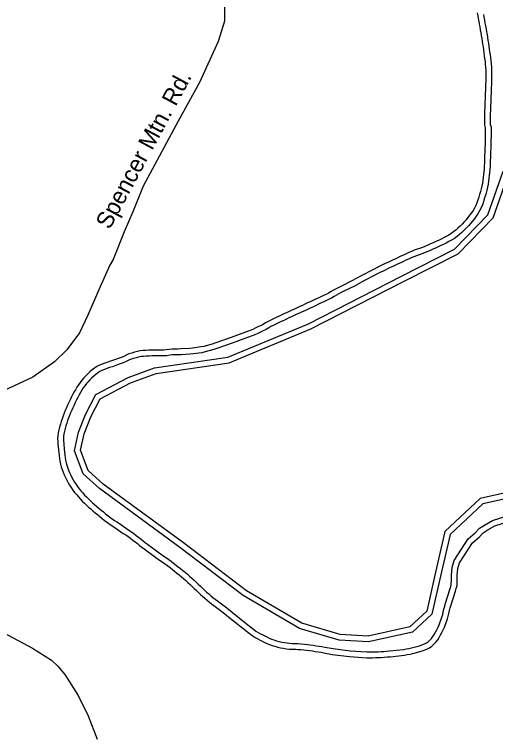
# Model space of a CAD drawing. Extents: x 1364363 to 1407445, y 538563 to 573342.
# Drawn here: x 1371427 to 1374145, y 564968 to 569065 of the extents above; entities that cross this region are included whole.
import ezdxf

# ---------------------------------------------------------------- set-up
doc = ezdxf.new("R2010")
doc.units = 0
for name, color, linetype in [('Exist Hydrographic Buffer Line', 7, 'Continuous'), ('Exist Hydrographic Creek Double Shore', 7, 'Continuous'), ('Exist Road Secondary Type 51 Attributed', 7, 'Continuous'), ('Exist Road Secondary Type 51 Label', 7, 'Continuous')]:
    doc.layers.add(name, color=color, linetype=linetype)

msp = doc.modelspace()

# ---------------------------------------------------------------- linework, layer by layer
at = {"layer": 'Exist Hydrographic Buffer Line'}
for points in [[(1374076.3, 569064.9), (1374079.3, 569048.8), (1374082.4, 569032.7), (1374085.4, 569016.4), (1374088.3, 569000.3), (1374091.3, 568983.9), (1374094.2, 568967.3), (1374096.8, 568950.9), (1374099.3, 568934.7), (1374101.9, 568918.5), (1374104.5, 568902.2), (1374107, 568885.8), (1374109.3, 568869.4), (1374111.7, 568853.1), (1374114, 568836.5), (1374116.1, 568819.9), (1374118.1, 568803.5), (1374120, 568786.6), (1374121.5, 568769.4), (1374122.5, 568751.9), (1374122.8, 568734.5), (1374122.8, 568717.5), (1374122.5, 568700.7), (1374122.2, 568684.2), (1374121.8, 568667.5), (1374121.1, 568650.9), (1374120.5, 568634.5), (1374119.9, 568618), (1374119.2, 568601.6), (1374118.6, 568585.2), (1374117.9, 568568.7), (1374117.1, 568552.4), (1374116.5, 568536.1), (1374115.9, 568520), (1374115.5, 568503.8), (1374115.1, 568487.4), (1374114.8, 568471.5), (1374114.9, 568455.9), (1374115.4, 568443.7), (1374119.5, 568427.8), (1374119.7, 568407.1), (1374119.5, 568390.1), (1374118.3, 568338.3), (1374116, 568256.1), (1374115.5, 568239.6), (1374115, 568223.1), (1374114.3, 568206.3), (1374113.4, 568188.7), (1374103.3, 568105.6), (1374100.2, 568087.6), (1374096, 568069.8), (1374091.3, 568053.4)], [(1374268.4, 566339.1), (1374074.1, 566297.1), (1373889, 566122.4), (1373833.5, 565886.1), (1373785.8, 565671.5), (1373676.3, 565569.8), (1373427.3, 565515), (1373261, 565525.3), (1373037.6, 565590.9), (1372719.5, 565777.5), (1372361.6, 566048.5), (1371906.2, 566382.4), (1371815.1, 566466.2), (1371765.6, 566596.4), (1371788.9, 566701.2), (1371827.8, 566801.1), (1371887, 566914.9), (1372068.6, 567011.8), (1372218.3, 567064.9), (1372631.3, 567126.2), (1373087.9, 567315.2), (1373613.4, 567584.4), (1373913.2, 567736.6), (1374102.2, 567932.2), (1374188.8, 568178.4)], [(1374091.2, 568053), (1374086.4, 568037), (1374081.4, 568021), (1374076.1, 568004.8), (1374070.4, 567988.6), (1374063.9, 567971.5), (1374055.2, 567953.8), (1374045, 567937.6), (1374035.1, 567923.5), (1374025.2, 567909.6), (1374014.6, 567895.7), (1374003.4, 567881.9), (1373991.5, 567868.7), (1373979.6, 567856.3), (1373967.5, 567844.1), (1373955, 567832), (1373941.7, 567819.9), (1373927.3, 567808.3), (1373912.2, 567797.6), (1373896.8, 567788.2), (1373881.7, 567779.8), (1373866.5, 567771.8), (1373851.2, 567764.3), (1373836, 567757), (1373820.6, 567750), (1373805.2, 567743.2), (1373789.9, 567736.5), (1373774.8, 567730), (1373743.5, 567716.7), (1373697.6, 567700), (1373683.5, 567693.9), (1373668.7, 567687.3), (1373653.9, 567680.7), (1373639, 567673.9), (1373624.2, 567667.2), (1373609.4, 567660.4), (1373594.6, 567653.4), (1373579.6, 567646.5), (1373564.9, 567639.7), (1373550.2, 567632.7), (1373535.4, 567625.7), (1373520.8, 567618.7), (1373506.2, 567611.6), (1373491.6, 567604.4), (1373477.2, 567597.2), (1373463, 567589.9), (1373405.3, 567559.1), (1373347.1, 567528.6), (1373288.4, 567498.5), (1373273.5, 567491.2), (1373259, 567483.9), (1373245.7, 567477.1), (1373233.1, 567469.3), (1373217.8, 567459.6), (1373201.1, 567451.7), (1373186.3, 567444.7), (1373171.4, 567437.6), (1373156.4, 567430.6), (1373141.6, 567423.7), (1373126.7, 567416.7), (1373111.8, 567409.7), (1373096.9, 567402.9), (1373082, 567395.9), (1373067, 567389.1), (1373052.2, 567382.2), (1373037.2, 567375.3), (1373022.3, 567368.4), (1373007.5, 567361.5), (1372992.6, 567354.6), (1372977.7, 567347.7), (1372962.9, 567340.8), (1372948, 567333.9), (1372933.1, 567326.9), (1372918.4, 567320), (1372903.7, 567313), (1372888.8, 567306), (1372875.5, 567299.7), (1372863.1, 567292.2), (1372848, 567282.8), (1372831.8, 567274.7), (1372816.6, 567267.4), (1372801.3, 567260.2), (1372785.2, 567253), (1372708.1, 567223.7), (1372661.9, 567206.5), (1372569.2, 567174.3), (1372552.6, 567168.7), (1372504.1, 567155.5), (1372486, 567151.3), (1372435.4, 567144), (1372417.6, 567142.8), (1372368.5, 567140.1), (1372351.5, 567139.2), (1372334.5, 567138.9), (1372317.6, 567138.6)], [(1372321.8, 567139), (1372305.2, 567136.6), (1372287.3, 567134.4), (1372269.3, 567133.6), (1372252.4, 567133.3), (1372235.6, 567133.1), (1372219.2, 567133), (1372203, 567132.8), (1372187.1, 567132.5), (1372171.6, 567131.8), (1372156.5, 567130.7), (1372142.1, 567129), (1372128.2, 567126.3), (1372113.9, 567122.6), (1372098.9, 567118.1), (1372085.1, 567113.8), (1372072.5, 567108.3), (1372057.3, 567100.6), (1372040.3, 567094), (1372024.5, 567088), (1372009, 567082.4), (1371980, 567072)], [(1371979.1, 567071.7), (1371963.7, 567066.7), (1371949.1, 567061.8), (1371934.7, 567056), (1371920.4, 567050.3), (1371908.6, 567044.5), (1371897.8, 567037.5), (1371886.3, 567028.6), (1371874.6, 567018.9), (1371863.4, 567008.7), (1371852.5, 566998), (1371842.2, 566987.2), (1371832.8, 566976.2), (1371824, 566964.5), (1371815.3, 566951.9), (1371806.9, 566938.8), (1371798.9, 566925.6), (1371791.4, 566912.3), (1371784.3, 566898.5), (1371777.3, 566884.2), (1371770.4, 566869.6), (1371763.5, 566854.9), (1371756.6, 566840.2), (1371749.9, 566825.5), (1371743.5, 566811), (1371737.6, 566796.6), (1371732.1, 566782.2), (1371727, 566767.5), (1371722, 566752.3), (1371717.3, 566737.2), (1371713, 566722.2), (1371709.3, 566707.2), (1371705.9, 566692.3), (1371703.5, 566678.9), (1371702.8, 566666.2), (1371703.4, 566651.8), (1371704.6, 566636.2), (1371707.7, 566604.7), (1371710.9, 566573.4), (1371713, 566558.3), (1371715.6, 566543.1), (1371718.5, 566528.9), (1371722.5, 566515.1), (1371732, 566486.6), (1371737.9, 566473.4), (1371744.5, 566459.1), (1371751.4, 566445.2), (1371758.6, 566431.8), (1371766.3, 566418.7), (1371774.5, 566405.8), (1371783.1, 566393.5), (1371792.3, 566381.3), (1371802, 566369.2), (1371812, 566357.5), (1371822.4, 566346.1), (1371833.1, 566334.9), (1371844.3, 566323.9), (1371855.8, 566313), (1371867.5, 566302.2), (1371879.3, 566291.7), (1371891.5, 566281.3), (1371903.7, 566270.9), (1371916.3, 566260.6), (1371928.9, 566250.2), (1371941.3, 566240.1), (1371953.5, 566230.4), (1371966.1, 566221.2), (1371979.2, 566211.9), (1371992.4, 566202.6), (1372005.8, 566193.4), (1372019.3, 566184.1), (1372032.8, 566174.8), (1372046.3, 566165.6), (1372059.9, 566156.3), (1372073.6, 566146.8), (1372087.1, 566137.4), (1372100.7, 566127.8), (1372114.6, 566117.8), (1372128.3, 566107.4), (1372141.6, 566096.7), (1372154.2, 566086.2), (1372166.4, 566076.4), (1372178.9, 566067.1), (1372244.7, 566019.2), (1372257.7, 566010), (1372271.1, 566000.8), (1372284.8, 565991.5), (1372298.8, 565981.6), (1372312.4, 565971.4), (1372325.8, 565961.2), (1372351.9, 565940.6), (1372364.9, 565930.1), (1372377.8, 565919.6), (1372390.6, 565908.9), (1372403.4, 565898.1), (1372416.1, 565887.1), (1372428.8, 565875.8), (1372441.1, 565864.3), (1372453.2, 565853)], [(1373017.6, 565506), (1373029.9, 565505.6), (1373047.3, 565504.6), (1373064.8, 565503), (1373081.7, 565500.9), (1373098.3, 565498.7), (1373114.9, 565496.3), (1373131.4, 565493.7), (1373147.7, 565491.1), (1373164.1, 565488.4), (1373180.6, 565485.6), (1373227.7, 565476.9), (1373322.7, 565464.6), (1373418.5, 565458), (1373433.5, 565458.1), (1373449.6, 565458.4), (1373465.6, 565458.9), (1373481.7, 565459.5), (1373497.8, 565460.3), (1373513.9, 565461.3), (1373529.7, 565462.4), (1373545.3, 565463.9), (1373625.6, 565472.9), (1373640.6, 565475.3), (1373655.9, 565478.1), (1373670.6, 565481.3), (1373715.4, 565493.6), (1373728.8, 565498.5), (1373743.1, 565504.4), (1373754.8, 565509.6), (1373763.8, 565516), (1373773.7, 565525), (1373783.4, 565535.1), (1373791.4, 565545.1), (1373798.5, 565556.6), (1373805.9, 565570), (1373813.1, 565583.9), (1373820, 565597.9), (1373826, 565611.1), (1373842, 565655.4), (1373846.4, 565669.2), (1373849.9, 565683.9), (1373853.6, 565699.8), (1373857.6, 565716.6), (1373862.4, 565733.4), (1373886.6, 565812), (1373891.6, 565827.7), (1373895, 565838.7), (1373895.2, 565866.7), (1373895.2, 565893.5), (1373900.3, 565936.8), (1373911.4, 565975.8), (1373989.5, 566097.9), (1374030.4, 566131.6), (1374054.8, 566158.4), (1374081.9, 566174.7), (1374128.2, 566201.5), (1374216.8, 566231.1)], [(1372453.3, 565852.8), (1372465.3, 565841.5), (1372477.1, 565830.1), (1372488.8, 565818.9), (1372500.6, 565807.9), (1372512.4, 565797.1), (1372524.2, 565786.6), (1372536.2, 565776.2), (1372548.3, 565766.2), (1372560.7, 565756.4), (1372573.3, 565746.9), (1372626.6, 565707.9), (1372678.3, 565666.1), (1372754.6, 565604), (1372767.1, 565593.7), (1372779.1, 565584.3), (1372791, 565575.7), (1372803, 565568.2), (1372816, 565561.3), (1372830.3, 565554.3), (1372852.3, 565543.4)], [(1372853.1, 565542.9), (1372866.6, 565535.8), (1372878.8, 565530.4), (1372892.5, 565526.2), (1372907.7, 565521.7), (1372922.8, 565517.6), (1372937.7, 565514), (1372952.3, 565511.1), (1372966.8, 565508.9), (1372981.5, 565507.6), (1372997, 565506.8), (1373013.2, 565506.2), (1373017.6, 565506)]]:
    msp.add_lwpolyline(points, dxfattribs=at)
at = {"layer": 'Exist Hydrographic Creek Double Shore'}
for points in [[(1374041.1, 569075), (1374044.1, 569059)], [(1374044.1, 569059), (1374047, 569042.8), (1374050.1, 569026.7), (1374053.1, 569010.5), (1374056.1, 568994.4), (1374059, 568978.2), (1374061.8, 568962), (1374064.4, 568945.8), (1374066.9, 568929.6), (1374069.5, 568913.4), (1374072.1, 568897.2), (1374074.5, 568881), (1374076.9, 568864.7), (1374079.2, 568848.5), (1374081.5, 568832.2), (1374083.5, 568815.9), (1374085.5, 568799.7), (1374087.3, 568783.4), (1374088.8, 568767), (1374089.7, 568750.7), (1374090, 568734.2), (1374090, 568717.8), (1374089.7, 568701.3), (1374089.4, 568684.9), (1374089, 568668.5), (1374088.4, 568652.2), (1374087.7, 568635.8), (1374087.1, 568619.4), (1374086.4, 568603), (1374085.8, 568586.6), (1374085.1, 568570.2), (1374084.4, 568553.8), (1374083.7, 568537.4), (1374083.1, 568521), (1374082.7, 568504.6), (1374082.3, 568488.1), (1374082, 568471.7), (1374082.1, 568455.2), (1374082.7, 568438.9), (1374086.7, 568423.4), (1374086.9, 568407.1), (1374086.7, 568390.7), (1374085.5, 568339.1), (1374083.2, 568257), (1374082.7, 568240.6), (1374082.2, 568224.3), (1374081.5, 568207.9), (1374080.7, 568191.5), (1374070.8, 568110.3), (1374068.1, 568094.1), (1374064.3, 568078.1), (1374059.8, 568062.4)], [(1374268.6, 566372.7), (1374058.3, 566327.2), (1373859.3, 566139.5), (1373801.5, 565893.4), (1373756, 565688.6), (1373660.5, 565599.9), (1373424.7, 565548.1), (1373266.7, 565557.8), (1373050.7, 565621.3), (1372737.8, 565804.8), (1372381.2, 566074.8), (1371927.1, 566407.8), (1371843, 566485.2), (1371799.8, 566598.9), (1371820.4, 566691.6), (1371857.7, 566787.5), (1371911.4, 566890.7), (1372081.9, 566981.7), (1372226.3, 567032.9), (1372640.1, 567094.3), (1373101.7, 567285.4), (1373628.3, 567555.1), (1373933, 567709.8), (1374130.8, 567914.6), (1374221.6, 568172.6)], [(1374059.8, 568062.4), (1374055, 568046.7), (1374050.1, 568031), (1374045, 568015.3), (1374039.6, 567999.9), (1374033.7, 567984.6), (1374026.5, 567969.8), (1374017.7, 567955.9), (1374008.3, 567942.4), (1373998.7, 567929.1), (1373988.8, 567915.9), (1373978.4, 567903.2), (1373967.5, 567891.1), (1373956.1, 567879.2), (1373944.4, 567867.4), (1373932.5, 567855.9), (1373920.3, 567844.8), (1373907.5, 567834.5), (1373894.2, 567825), (1373880.3, 567816.6), (1373866.1, 567808.6), (1373851.6, 567801.1), (1373836.9, 567793.8), (1373822.1, 567786.7), (1373807.1, 567779.9), (1373792.1, 567773.2), (1373776.9, 567766.7), (1373761.8, 567760.2), (1373731.5, 567747.2), (1373685.4, 567730.5), (1373670.4, 567723.9), (1373655.4, 567717.3), (1373640.4, 567710.6), (1373625.5, 567703.8), (1373610.5, 567697), (1373595.6, 567690.1), (1373580.8, 567683.2), (1373565.8, 567676.3), (1373550.9, 567669.4), (1373536.2, 567662.3), (1373521.3, 567655.3), (1373506.5, 567648.2), (1373491.8, 567641.1), (1373477, 567633.8), (1373462.3, 567626.5), (1373447.8, 567619), (1373389.9, 567588.1), (1373332, 567557.8), (1373273.6, 567527.8), (1373258.9, 567520.5), (1373244.2, 567513.2), (1373229.6, 567505.7), (1373215.7, 567497.1), (1373201.9, 567488.4), (1373187.1, 567481.3), (1373172.3, 567474.3), (1373157.4, 567467.3), (1373142.6, 567460.3), (1373127.7, 567453.4), (1373112.8, 567446.4), (1373098, 567439.5), (1373083.1, 567432.6), (1373068.2, 567425.7), (1373053.3, 567418.8), (1373038.4, 567411.9), (1373023.5, 567405.1), (1373008.6, 567398.2), (1372993.7, 567391.3), (1372978.8, 567384.4), (1372963.9, 567377.5), (1372949, 567370.6), (1372934.1, 567363.6), (1372919.3, 567356.7), (1372904.4, 567349.7), (1372889.6, 567342.7), (1372874.8, 567335.6), (1372860, 567328.6), (1372845.9, 567320.2), (1372832, 567311.5), (1372817.3, 567304.2), (1372802.5, 567297), (1372787.6, 567290), (1372772.6, 567283.3), (1372696.6, 567254.4), (1372650.8, 567237.4), (1372558.7, 567205.3), (1372543.1, 567200.2), (1372496.1, 567187.3), (1372480, 567183.6), (1372431.9, 567176.7), (1372415.5, 567175.5), (1372366.7, 567172.8), (1372350.3, 567172), (1372333.9, 567171.7), (1372317.1, 567171.4)], [(1372317.1, 567171.4), (1372300.9, 567169.1), (1372284.6, 567167.1), (1372268.2, 567166.4), (1372251.8, 567166.1), (1372235.3, 567165.9), (1372218.9, 567165.8), (1372202.5, 567165.6), (1372186, 567165.2), (1372169.7, 567164.5), (1372153.4, 567163.3), (1372137.1, 567161.5), (1372121, 567158.3), (1372105.1, 567154.2), (1372089.3, 567149.5), (1372073.6, 567144.6), (1372058.5, 567138), (1372043.9, 567130.6), (1372028.6, 567124.6), (1372013.2, 567118.9), (1371997.9, 567113.3), (1371968.9, 567102.9)], [(1371968.9, 567102.9), (1371953.4, 567097.8), (1371937.8, 567092.6), (1371922.5, 567086.5), (1371907.1, 567080.3), (1371892.4, 567073.1), (1371878.7, 567064.2), (1371865.8, 567054.2), (1371853.1, 567043.6), (1371840.9, 567032.6), (1371829.1, 567021), (1371817.8, 567009.2), (1371807.2, 566996.7), (1371797.3, 566983.6), (1371788, 566970), (1371779.1, 566956.1), (1371770.6, 566942.1), (1371762.6, 566927.8), (1371755, 566913.2), (1371747.8, 566898.5), (1371740.7, 566883.7), (1371733.7, 566868.8), (1371726.8, 566853.9), (1371720, 566839), (1371713.3, 566823.9), (1371707.1, 566808.8), (1371701.2, 566793.4), (1371695.9, 566778), (1371690.8, 566762.3), (1371685.9, 566746.5), (1371681.4, 566730.7), (1371677.4, 566714.7), (1371673.8, 566698.8), (1371670.9, 566682.8), (1371670, 566666.4), (1371670.7, 566649.8), (1371671.9, 566633.4), (1371675.1, 566601.4), (1371678.3, 566569.5), (1371680.5, 566553.3), (1371683.3, 566537.1), (1371686.6, 566521), (1371691.2, 566505.3), (1371701.3, 566474.8), (1371708, 566459.8), (1371715, 566444.9), (1371722.3, 566430.1), (1371730.1, 566415.7), (1371738.4, 566401.5), (1371747.2, 566387.7), (1371756.5, 566374.2), (1371766.4, 566361.1), (1371776.7, 566348.3), (1371787.4, 566335.8), (1371798.4, 566323.7), (1371809.8, 566311.8), (1371821.5, 566300.3), (1371833.4, 566289.1), (1371845.5, 566277.9), (1371857.7, 566267), (1371870.2, 566256.3), (1371882.7, 566245.7), (1371895.4, 566235.3), (1371908, 566224.9), (1371920.8, 566214.5), (1371933.7, 566204.3), (1371946.9, 566194.6), (1371960.2, 566185.1), (1371973.7, 566175.7), (1371987.2, 566166.3), (1372000.7, 566157.1), (1372014.3, 566147.8), (1372027.8, 566138.5), (1372041.3, 566129.2), (1372054.9, 566119.9), (1372068.3, 566110.5), (1372081.7, 566101.1), (1372095, 566091.5), (1372108.1, 566081.5), (1372120.9, 566071.2), (1372133.5, 566060.8), (1372146.3, 566050.5), (1372159.4, 566040.7), (1372225.6, 565992.5), (1372239, 565983.1), (1372252.5, 565973.8), (1372266.1, 565964.5), (1372279.5, 565955.1), (1372292.6, 565945.2), (1372305.6, 565935.2), (1372318.6, 565925.1), (1372331.5, 565914.9), (1372344.2, 565904.6), (1372356.9, 565894.2), (1372369.5, 565883.8), (1372382, 565873.2), (1372394.4, 565862.4), (1372406.7, 565851.5), (1372418.7, 565840.4), (1372430.7, 565829.1)], [(1373016.4, 565473.3), (1373028.4, 565472.8), (1373044.8, 565471.9), (1373061.3, 565470.4), (1373077.4, 565468.4), (1373093.8, 565466.2), (1373110.1, 565463.8), (1373126.3, 565461.3), (1373142.5, 565458.7), (1373158.7, 565456), (1373174.8, 565453.3), (1373222.6, 565444.5), (1373319.5, 565431.9), (1373417.5, 565425.2), (1373433.9, 565425.3), (1373450.3, 565425.6), (1373466.7, 565426.1), (1373483.1, 565426.8), (1373499.5, 565427.6), (1373516, 565428.6), (1373532.4, 565429.7), (1373548.7, 565431.2), (1373630, 565440.4), (1373646.2, 565443), (1373662.4, 565445.9), (1373678.5, 565449.4), (1373725.4, 565462.3), (1373740.8, 565468), (1373756.1, 565474.3), (1373771.1, 565481), (1373784.5, 565490.4), (1373796.6, 565501.5), (1373808.1, 565513.3), (1373818.3, 565526.1), (1373826.9, 565540.1), (1373834.8, 565554.5), (1373842.4, 565569.1), (1373849.7, 565583.8), (1373856.4, 565598.7), (1373873.1, 565644.8), (1373878, 565660.4), (1373881.9, 565676.3), (1373885.6, 565692.4), (1373889.4, 565708.3), (1373893.9, 565724.1), (1373918, 565802.2), (1373922.9, 565817.9), (1373927.8, 565833.5), (1373928, 565866.6), (1373928, 565891.6), (1373932.5, 565930.3), (1373941.6, 565962.1), (1374014.4, 566075.9), (1374053.1, 566107.7), (1374075.8, 566132.8), (1374098.5, 566146.4), (1374141.7, 566171.4), (1374223.6, 566198.7)], [(1372430.7, 565829.1), (1372442.6, 565817.7), (1372454.4, 565806.4), (1372466.3, 565795.1), (1372478.3, 565783.9), (1372490.4, 565772.8), (1372502.6, 565761.9), (1372515.1, 565751.2), (1372527.7, 565740.7), (1372540.6, 565730.5), (1372553.6, 565720.6), (1372606.5, 565681.9), (1372657.6, 565640.6), (1372733.8, 565578.6), (1372746.5, 565568.1), (1372759.4, 565558), (1372772.7, 565548.5), (1372786.6, 565539.8), (1372801, 565532.1), (1372815.8, 565524.8), (1372837.7, 565514)], [(1372837.7, 565514), (1372852.3, 565506.2), (1372867.3, 565499.7), (1372883, 565494.8), (1372898.7, 565490.1), (1372914.6, 565485.8), (1372930.6, 565481.9), (1372946.7, 565478.7), (1372962.9, 565476.3), (1372979.1, 565474.8), (1372995.5, 565474), (1373012, 565473.4), (1373016.4, 565473.3)]]:
    msp.add_lwpolyline(points, dxfattribs=at)
at = {"layer": 'Exist Road Secondary Type 51 Attributed'}
for points in [[(1372614.2, 569128), (1372614.2, 569026.9), (1372577.8, 568911.9), (1372471.8, 568679.9), (1372350.9, 568461.2), (1372153.8, 568093.3), (1372095.9, 567947.5), (1372046.2, 567834.8), (1371983.3, 567679), (1371965.1, 567645.9), (1371908.7, 567519.6), (1371840.8, 567363.9), (1371794.5, 567262.8), (1371723.3, 567166.7), (1371652.1, 567098.7), (1371529.5, 567012.6), (1371151.3, 566836.9)], [(1371166.3, 565671.8), (1371527.9, 565479.4), (1371635.5, 565411.5), (1371671.9, 565378.3), (1371711.7, 565330.3), (1371786.2, 565212.6), (1371843.6, 565097.5), (1371893.8, 564965.4)]]:
    msp.add_lwpolyline(points, dxfattribs=at)

# ---------------------------------------------------------------- texts
at = {"layer": 'Exist Road Secondary Type 51 Label'}
msp.add_text('Spencer Mtn. Rd.', height=95, rotation=61.822, dxfattribs=at).set_placement((1371964.2, 567843.5))

doc.saveas('drawing.dxf')
